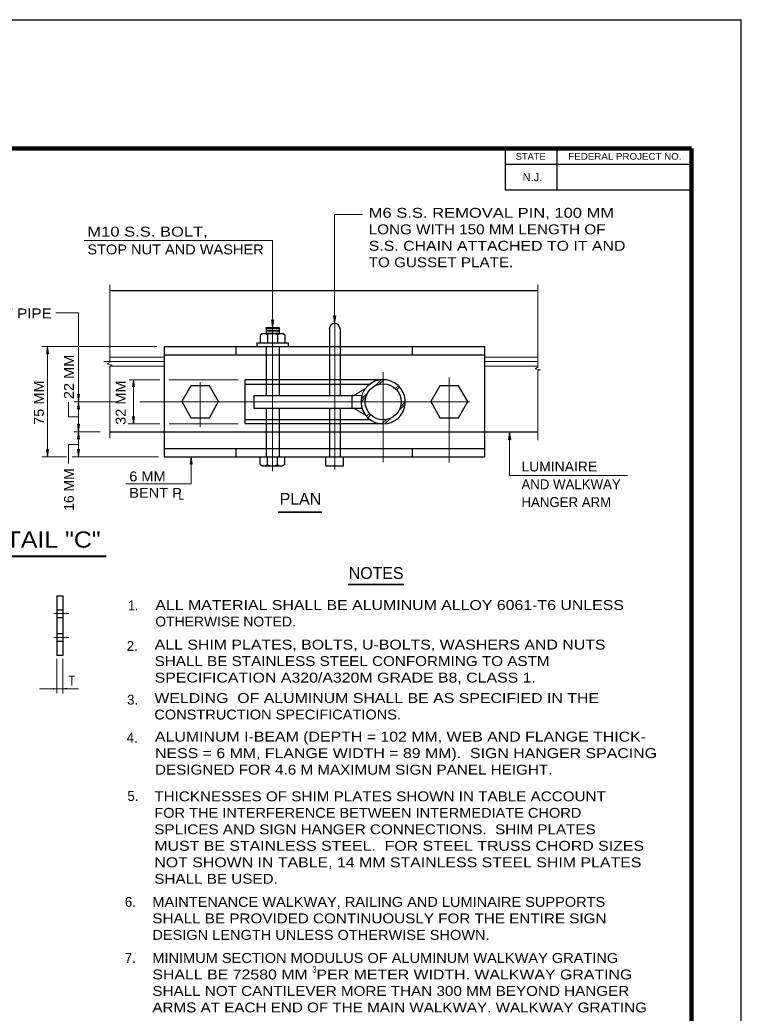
# Model space of a CAD drawing. Extents: x 312601.858 to 312602.699, y 144420.109 to 144420.704.
# Drawn here: x 312602.4801 to 312602.6988, y 144420.4024 to 144420.7035 of the extents above; entities that cross this region are included whole.
import ezdxf
from ezdxf.enums import TextEntityAlignment as Align

# ---------------------------------------------------------------- set-up
doc = ezdxf.new("R2010")
doc.units = 0
doc.header["$LTSCALE"] = 0.0012
for name, pattern in [('DOT_DASHED', [7.7, 5, -1.2, 0.3, -1.2]), ('LONG_DASHED', [7.5, 6, -1.5]), ('SHORT_DASHED', [2.7, 1.5, -1.2])]:
    doc.linetypes.add(name, pattern=pattern)
for name, color, linetype, lineweight in [('1', 7, 'Continuous', 13), ('2', 7, 'Continuous', 13), ('39', 7, 'Continuous', 13), ('61', 7, 'Continuous', 25)]:
    doc.layers.add(name, color=color, linetype=linetype, lineweight=lineweight)

msp = doc.modelspace()

# ---------------------------------------------------------------- hatches: boundary and pattern name
at = {"layer": '39'}
for points in [[(312602.5567, 144420.6124), (312602.5571, 144420.6126), (312602.5567, 144420.6102), (312602.5564, 144420.6126)], [(312602.5755, 144420.6136), (312602.5759, 144420.6138), (312602.5755, 144420.6114), (312602.5752, 144420.6138)], [(312602.6286, 144420.5764), (312602.6283, 144420.5762), (312602.6286, 144420.5786), (312602.629, 144420.5762)]]:
    msp.add_hatch(color=256, dxfattribs=at).paths.add_polyline_path(points)

# ---------------------------------------------------------------- linework, layer by layer
at = {"layer": '1'}
for p, q in [((312602.5755, 144420.6445), (312602.5755, 144420.6114)), ((312602.5757, 144420.6445), (312602.584, 144420.6445)), ((312602.4996, 144420.6366), (312602.5567, 144420.6366)), ((312602.5567, 144420.6366), (312602.5567, 144420.6102)), ((312602.5074, 144420.6232), (312602.5074, 144420.5997)), ((312602.6372, 144420.6233), (312602.6372, 144420.5982)), ((312602.5548, 144420.6098), (312602.5587, 144420.6098)), ((312602.5548, 144420.6093), (312602.5587, 144420.6093)), ((312602.5548, 144420.6089), (312602.5587, 144420.6089)), ((312602.4868, 144420.6045), (312602.5217, 144420.6045)), ((312602.4885, 144420.6045), (312602.4885, 144420.571)), ((312602.5066, 144420.5992), (312602.5073, 144420.5996)), ((312602.5066, 144420.5992), (312602.5081, 144420.5988)), ((312602.5074, 144420.5985), (312602.5081, 144420.5988)), ((312602.5074, 144420.5985), (312602.5074, 144420.5767)), ((312602.6364, 144420.5977), (312602.6372, 144420.5982)), ((312602.6364, 144420.5977), (312602.638, 144420.5974)), ((312602.6372, 144420.5971), (312602.638, 144420.5974)), ((312602.6372, 144420.5971), (312602.6372, 144420.5761)), ((312602.5226, 144420.5944), (312602.5133, 144420.5944)), ((312602.5146, 144420.5944), (312602.5146, 144420.581)), ((312602.5463, 144420.5944), (312602.5253, 144420.5944)), ((312602.5877, 144420.5925), (312602.5897, 144420.5944)), ((312602.589, 144420.593), (312602.5905, 144420.5944)), ((312602.5837, 144420.5886), (312602.5855, 144420.5903)), ((312602.5848, 144420.5916), (312602.5849, 144420.5917)), ((312602.5939, 144420.5917), (312602.5949, 144420.5926)), ((312602.5944, 144420.5913), (312602.5953, 144420.5922)), ((312602.4966, 144420.5877), (312602.5095, 144420.5877)), ((312602.5836, 144420.5877), (312602.585, 144420.5892)), ((312602.5956, 144420.5863), (312602.597, 144420.5878)), ((312602.5852, 144420.5834), (312602.5861, 144420.5842)), ((312602.5951, 144420.5852), (312602.5969, 144420.5869)), ((312602.5226, 144420.581), (312602.513, 144420.581)), ((312602.5463, 144420.581), (312602.5254, 144420.581)), ((312602.5848, 144420.5838), (312602.5849, 144420.5837)), ((312602.5856, 144420.5829), (312602.5865, 144420.5838)), ((312602.5899, 144420.581), (312602.5914, 144420.5824)), ((312602.5908, 144420.581), (312602.5927, 144420.5829)), ((312602.4965, 144420.5786), (312602.5045, 144420.5786)), ((312602.4868, 144420.571), (312602.4943, 144420.571)), ((312602.496, 144420.571), (312602.5222, 144420.571)), ((312602.4913, 144420.5098), (312602.4913, 144420.4994)), ((312602.4932, 144420.5098), (312602.4932, 144420.4993))]:
    msp.add_line(p, q, dxfattribs=at)
at = {"layer": '1', "lineweight": 25}
for p, q in [((312602.5074, 144420.6215), (312602.6372, 144420.6215)), ((312602.553, 144420.608), (312602.5536, 144420.6084)), ((312602.5536, 144420.6084), (312602.5599, 144420.6084)), ((312602.5548, 144420.6102), (312602.5587, 144420.6102)), ((312602.5548, 144420.6102), (312602.5548, 144420.6084)), ((312602.5587, 144420.6102), (312602.5587, 144420.6084)), ((312602.5605, 144420.608), (312602.5599, 144420.6084)), ((312602.574, 144420.6098), (312602.574, 144420.6045)), ((312602.5772, 144420.6098), (312602.5772, 144420.6045)), ((312602.552, 144420.6056), (312602.552, 144420.6045)), ((312602.552, 144420.6056), (312602.5615, 144420.6056)), ((312602.553, 144420.608), (312602.553, 144420.6056)), ((312602.5552, 144420.608), (312602.5552, 144420.6056)), ((312602.5582, 144420.608), (312602.5582, 144420.6056)), ((312602.5605, 144420.608), (312602.5605, 144420.6056)), ((312602.5615, 144420.6056), (312602.5615, 144420.6045)), ((312602.5239, 144420.6045), (312602.621, 144420.6045)), ((312602.5239, 144420.6045), (312602.5239, 144420.571)), ((312602.5456, 144420.6045), (312602.5456, 144420.602)), ((312602.5991, 144420.6045), (312602.5991, 144420.602)), ((312602.621, 144420.6045), (312602.621, 144420.571)), ((312602.5239, 144420.602), (312602.621, 144420.602)), ((312602.5548, 144420.602), (312602.5548, 144420.5944)), ((312602.5587, 144420.602), (312602.5587, 144420.5944)), ((312602.574, 144420.602), (312602.574, 144420.5944)), ((312602.5772, 144420.602), (312602.5772, 144420.5944)), ((312602.5483, 144420.5944), (312602.5483, 144420.581)), ((312602.5903, 144420.5944), (312602.5484, 144420.5944)), ((312602.5511, 144420.5896), (312602.5511, 144420.5858)), ((312602.5511, 144420.5896), (312602.5814, 144420.5896)), ((312602.5808, 144420.5896), (312602.5808, 144420.5858)), ((312602.5511, 144420.5858), (312602.5838, 144420.5858)), ((312602.5903, 144420.581), (312602.5483, 144420.581)), ((312602.5548, 144420.581), (312602.5548, 144420.5736)), ((312602.5587, 144420.581), (312602.5587, 144420.5736)), ((312602.574, 144420.581), (312602.574, 144420.5736)), ((312602.5772, 144420.581), (312602.5772, 144420.5736)), ((312602.5074, 144420.5786), (312602.5239, 144420.5786)), ((312602.621, 144420.5786), (312602.6372, 144420.5786)), ((312602.5239, 144420.5736), (312602.621, 144420.5736)), ((312602.5456, 144420.5736), (312602.5456, 144420.571)), ((312602.5991, 144420.5736), (312602.5991, 144420.571)), ((312602.5239, 144420.571), (312602.621, 144420.571)), ((312602.553, 144420.5687), (312602.553, 144420.571)), ((312602.5552, 144420.5687), (312602.5552, 144420.571)), ((312602.5582, 144420.5687), (312602.5582, 144420.571)), ((312602.5605, 144420.5687), (312602.5605, 144420.571)), ((312602.5729, 144420.5683), (312602.5729, 144420.571)), ((312602.5782, 144420.5683), (312602.5782, 144420.571)), ((312602.553, 144420.5687), (312602.5536, 144420.5683)), ((312602.5536, 144420.5683), (312602.5599, 144420.5683)), ((312602.5605, 144420.5687), (312602.5599, 144420.5683)), ((312602.5729, 144420.5683), (312602.5782, 144420.5683)), ((312602.4913, 144420.5289), (312602.4913, 144420.5108)), ((312602.4913, 144420.5289), (312602.4932, 144420.5289)), ((312602.4932, 144420.5289), (312602.4932, 144420.5108)), ((312602.4913, 144420.5246), (312602.4932, 144420.5246)), ((312602.4913, 144420.5223), (312602.4932, 144420.5223)), ((312602.4913, 144420.5175), (312602.4932, 144420.5175)), ((312602.4913, 144420.5151), (312602.4932, 144420.5151)), ((312602.4932, 144420.5108), (312602.4913, 144420.5108))]:
    msp.add_line(p, q, dxfattribs=at)
at = {"layer": '1', "linetype": 'DOT_DASHED'}
for p, q in [((312602.5756, 144420.6113), (312602.5756, 144420.5672)), ((312602.5567, 144420.6104), (312602.5567, 144420.5667)), ((312602.5056, 144420.5999), (312602.5239, 144420.5999)), ((312602.621, 144420.5999), (312602.6372, 144420.5999)), ((312602.5903, 144420.5967), (312602.5903, 144420.5694)), ((312602.5348, 144420.5937), (312602.5348, 144420.5801)), ((312602.6103, 144420.5951), (312602.6103, 144420.5693)), ((312602.6103, 144420.5937), (312602.6103, 144420.5801)), ((312602.5165, 144420.5877), (312602.6184, 144420.5877)), ((312602.495, 144420.5235), (312602.4904, 144420.5235)), ((312602.495, 144420.5163), (312602.4904, 144420.5163))]:
    msp.add_line(p, q, dxfattribs=at)
at = {"layer": '1', "linetype": 'SHORT_DASHED', "lineweight": 25}
for p, q in [((312602.5548, 144420.6045), (312602.5548, 144420.602)), ((312602.5587, 144420.6045), (312602.5587, 144420.602)), ((312602.574, 144420.6045), (312602.574, 144420.602)), ((312602.5772, 144420.6045), (312602.5772, 144420.602)), ((312602.5548, 144420.5944), (312602.5548, 144420.5896)), ((312602.5587, 144420.5944), (312602.5587, 144420.5896)), ((312602.574, 144420.5944), (312602.574, 144420.5896)), ((312602.5772, 144420.5944), (312602.5772, 144420.5896)), ((312602.5548, 144420.5858), (312602.5548, 144420.581)), ((312602.5587, 144420.5858), (312602.5587, 144420.581)), ((312602.574, 144420.5858), (312602.574, 144420.581)), ((312602.5772, 144420.5858), (312602.5772, 144420.581)), ((312602.5548, 144420.5736), (312602.5548, 144420.571)), ((312602.5587, 144420.5736), (312602.5587, 144420.571)), ((312602.574, 144420.5736), (312602.574, 144420.571)), ((312602.5772, 144420.5736), (312602.5772, 144420.571))]:
    msp.add_line(p, q, dxfattribs=at)
at = {"layer": '1', "linetype": 'LONG_DASHED'}
for p, q in [((312602.5074, 144420.6012), (312602.5239, 144420.6012)), ((312602.621, 144420.6012), (312602.6372, 144420.6012)), ((312602.5074, 144420.5985), (312602.5239, 144420.5985)), ((312602.621, 144420.5985), (312602.6372, 144420.5985))]:
    msp.add_line(p, q, dxfattribs=at)
at = {"layer": '1', "linetype": 'LONG_DASHED', "lineweight": 25}
for p, q in [((312602.5483, 144420.5931), (312602.5864, 144420.5931)), ((312602.5483, 144420.5823), (312602.5864, 144420.5823)), ((312602.5242, 144420.5786), (312602.621, 144420.5786))]:
    msp.add_line(p, q, dxfattribs=at)
at = {"layer": '1'}
for points in [[(312602.4979, 144420.6147), (312602.4979, 144420.5877), (312602.4979, 144420.5786), (312602.4979, 144420.571)], [(312602.5849, 144420.5917), (312602.5814, 144420.5896), (312602.5838, 144420.5896)], [(312602.5838, 144420.5896), (312602.5814, 144420.5896), (312602.5849, 144420.5917), (312602.5848, 144420.5916)], [(312602.5849, 144420.5837), (312602.5814, 144420.5858), (312602.5838, 144420.5858)], [(312602.6286, 144420.5786), (312602.6286, 144420.5654), (312602.6643, 144420.5654)], [(312602.5321, 144420.571), (312602.5321, 144420.5628), (312602.5123, 144420.5628)], [(312602.4861, 144420.5007), (312602.4913, 144420.5007), (312602.4932, 144420.5007), (312602.4979, 144420.5007)]]:
    msp.add_lwpolyline(points, dxfattribs=at)
for points in [[(312602.4882, 144420.6023), (312602.4885, 144420.6045), (312602.4888, 144420.6023), (312602.4885, 144420.6025)], [(312602.5143, 144420.5922), (312602.5146, 144420.5944), (312602.5149, 144420.5922), (312602.5146, 144420.5924)], [(312602.4982, 144420.59), (312602.4979, 144420.5877), (312602.4976, 144420.59), (312602.4979, 144420.5897)], [(312602.4976, 144420.5855), (312602.4979, 144420.5877), (312602.4982, 144420.5855), (312602.4979, 144420.5857)], [(312602.5149, 144420.5833), (312602.5146, 144420.581), (312602.5143, 144420.5833), (312602.5146, 144420.583)], [(312602.4982, 144420.5809), (312602.4979, 144420.5786), (312602.4976, 144420.5809), (312602.4979, 144420.5806)], [(312602.4976, 144420.5764), (312602.4979, 144420.5786), (312602.4982, 144420.5764), (312602.4979, 144420.5766)], [(312602.4888, 144420.5733), (312602.4885, 144420.571), (312602.4882, 144420.5733), (312602.4885, 144420.573)], [(312602.4982, 144420.5733), (312602.4979, 144420.571), (312602.4976, 144420.5733), (312602.4979, 144420.573)], [(312602.5318, 144420.5688), (312602.5321, 144420.571), (312602.5324, 144420.5688), (312602.5321, 144420.569)]]:
    msp.add_lwpolyline(points, close=True, dxfattribs=at)
at = {"layer": '1', "lineweight": 25}
for points in [[(312602.532, 144420.5829), (312602.5376, 144420.5829), (312602.5404, 144420.5878), (312602.5376, 144420.5926), (312602.532, 144420.5926), (312602.5292, 144420.5878)], [(312602.6075, 144420.5829), (312602.6131, 144420.5829), (312602.6159, 144420.5878), (312602.6131, 144420.5926), (312602.6075, 144420.5926), (312602.6047, 144420.5878)]]:
    msp.add_lwpolyline(points, close=True, dxfattribs=at)
msp.add_circle((312602.590285, 144420.587705), 0.00544, dxfattribs=at)
for centre, radius, start, end in [((312602.554075, 144420.60649), 0.001872, 53.82173, 116.36509), ((312602.559345, 144420.60649), 0.001872, 56.30993, 126.17827), ((312602.590285, 144420.587705), 0.006715, 163.83043, 143.98606), ((312602.554075, 144420.570195), 0.001872, 243.63491, 306.17827), ((312602.559345, 144420.570195), 0.001872, 233.82173, 296.36509)]:
    msp.add_arc(centre, radius, start, end, dxfattribs=at)
at = {"layer": '1'}
for centre, radius, start, end in [((312602.55671, 144420.604747), 0.003612, 64.94239, 115.05762), ((312602.590285, 144420.587705), 0.006715, 143.98606, 163.83043), ((312602.590285, 144420.587705), 0.006715, 143.98606, 163.83043), ((312602.590285, 144420.587705), 0.006715, 196.16957, 216.01394), ((312602.55671, 144420.571938), 0.003612, 244.94238, 295.05761)]:
    msp.add_arc(centre, radius, start, end, dxfattribs=at)
at = {"layer": '1', "lineweight": 25}
msp.add_ellipse((312602.57558, 144420.609805), major_axis=(0.001623, 0.000171), ratio=0.995348, start_param=6.1788327, end_param=9.319901, dxfattribs=at)
at = {"layer": '2'}
for p, q in [((312602.4979, 144420.6147), (312602.491, 144420.6147)), ((312602.4979, 144420.5748), (312602.4949, 144420.5748)), ((312602.4949, 144420.569), (312602.4949, 144420.5748))]:
    msp.add_line(p, q, dxfattribs=at)
at = {"layer": '2', "lineweight": 35}
for p, q in [((312602.5584, 144420.5543), (312602.5717, 144420.5543)), ((312602.5797, 144420.5323), (312602.5965, 144420.5323))]:
    msp.add_line(p, q, dxfattribs=at)
at = {"layer": '2', "lineweight": 40}
msp.add_line((312602.3981, 144420.5409), (312602.5063, 144420.5409), dxfattribs=at)
at = {"layer": '2'}
msp.add_lwpolyline([(312602.4979, 144420.5832), (312602.4949, 144420.5832), (312602.4949, 144420.5876)], dxfattribs=at)
for points in [[(312602.4902, 144420.5008), (312602.4913, 144420.5007), (312602.4902, 144420.5006), (312602.4903, 144420.5007)], [(312602.4943, 144420.5006), (312602.4932, 144420.5007), (312602.4943, 144420.5009), (312602.4942, 144420.5007)]]:
    msp.add_lwpolyline(points, close=True, dxfattribs=at)
at = {"layer": '39', "lineweight": 25}
for p, q in [((312601.8578, 144420.7035), (312602.6988, 144420.7035)), ((312602.6988, 144420.1095), (312602.6988, 144420.7035)), ((312602.5735, 144420.6645), (312602.6838, 144420.6645)), ((312602.6838, 144420.6514), (312602.6838, 144420.6645))]:
    msp.add_line(p, q, dxfattribs=at)
at = {"layer": '39', "lineweight": 158}
for p in [(312601.9088, 144420.6645), (312602.6838, 144420.1247)]:
    msp.add_line(p, (312602.6838, 144420.6645), dxfattribs=at)
at = {"layer": '39'}
for points in [[(312602.5567, 144420.6124), (312602.5571, 144420.6126), (312602.5567, 144420.6102), (312602.5564, 144420.6126)], [(312602.5755, 144420.6136), (312602.5759, 144420.6138), (312602.5755, 144420.6114), (312602.5752, 144420.6138)], [(312602.6286, 144420.5764), (312602.6283, 144420.5762), (312602.6286, 144420.5786), (312602.629, 144420.5762)]]:
    msp.add_lwpolyline(points, close=True, dxfattribs=at)
at = {"layer": '61'}
for p, q in [((312602.6273, 144420.6645), (312602.6273, 144420.6519)), ((312602.6429, 144420.6645), (312602.6429, 144420.6519)), ((312602.6838, 144420.6597), (312602.6273, 144420.6597)), ((312602.6838, 144420.6519), (312602.6273, 144420.6519))]:
    msp.add_line(p, q, dxfattribs=at)

# ---------------------------------------------------------------- texts
at = {"layer": '2'}
for s, height, width, p in [('M6 S.S. REMOVAL PIN, 100 MM', 0.003, 1.25, (312602.5859, 144420.6435)), ('LONG WITH 150 MM LENGTH OF', 0.003, 1.15, (312602.5859, 144420.6385)), ('M10 S.S. BOLT,', 0.003, 1.25, (312602.5006, 144420.6378)), ('STOP NUT AND WASHER', 0.003, 1.1, (312602.5006, 144420.6324)), ('S.S. CHAIN ATTACHED TO IT AND', 0.003, 1.2, (312602.5859, 144420.6335)), ('TO GUSSET PLATE.', 0.003, 1.15, (312602.5859, 144420.6285)), ('OF PIPE', 0.003, 1.15, (312602.4716, 144420.613)), ('LUMINAIRE', 0.003, 1.05, (312602.6322, 144420.5666)), ('6 MM', 0.003, 1.1, (312602.5133, 144420.5636)), ('BENT P', 0.003, 1.1, (312602.5133, 144420.5586)), ('HANDRAIL HINGE DETAIL "C"', 0.0049, 1.15, (312602.3992, 144420.5435)), ('ALL MATERIAL SHALL BE ALUMINUM ALLOY 6061-T6 UNLESS', 0.003, 1.2, (312602.5212, 144420.5246)), ('OTHERWISE NOTED.', 0.003, 1.05, (312602.5212, 144420.5196)), ('ALL SHIM PLATES, BOLTS, U-BOLTS, WASHERS AND NUTS', 0.003, 1.2, (312602.521, 144420.5126)), ('SHALL BE STAINLESS STEEL CONFORMING TO ASTM ', 0.003, 1.15, (312602.521, 144420.5076)), ('SPECIFICATION A320/A320M GRADE B8, CLASS 1.', 0.003, 1.2, (312602.521, 144420.5026)), ('WELDING  OF ALUMINUM SHALL BE AS SPECIFIED IN THE', 0.003, 1.2, (312602.5209, 144420.4964)), ('CONSTRUCTION SPECIFICATIONS.', 0.003, 1.1, (312602.5209, 144420.4914)), ('ALUMINUM I-BEAM (DEPTH = 102 MM, WEB AND FLANGE THICK-', 0.003, 1.2, (312602.5211, 144420.4847)), ('NESS = 6 MM, FLANGE WIDTH = 89 MM).  SIGN HANGER SPACING', 0.003, 1.2, (312602.5211, 144420.4797)), ('DESIGNED FOR 4.6 M MAXIMUM SIGN PANEL HEIGHT.', 0.003, 1.15, (312602.5211, 144420.4747)), ('THICKNESSES OF SHIM PLATES SHOWN IN TABLE ACCOUNT', 0.003, 1.15, (312602.5209, 144420.4666)), ('FOR THE INTERFERENCE BETWEEN INTERMEDIATE CHORD', 0.003, 1.1, (312602.5209, 144420.4616)), ('SPLICES AND SIGN HANGER CONNECTIONS.  SHIM PLATES', 0.003, 1.15, (312602.5209, 144420.4566)), ('MUST BE STAINLESS STEEL.  FOR STEEL TRUSS CHORD SIZES', 0.003, 1.2, (312602.5209, 144420.4516)), ('NOT SHOWN IN TABLE, 14 MM STAINLESS STEEL SHIM PLATES', 0.003, 1.2, (312602.5209, 144420.4466)), ('SHALL BE USED.', 0.003, 1.15, (312602.5209, 144420.4416)), ('MAINTENANCE WALKWAY, RAILING AND LUMINAIRE SUPPORTS', 0.003, 1.1, (312602.5203, 144420.4346)), ('SHALL BE PROVIDED CONTINUOUSLY FOR THE ENTIRE SIGN', 0.003, 1.15, (312602.5203, 144420.4296)), ('DESIGN LENGTH UNLESS OTHERWISE SHOWN.', 0.003, 1.1, (312602.5203, 144420.4246)), ('MINIMUM SECTION MODULUS OF ALUMINUM WALKWAY GRATING', 0.003, 1.1, (312602.5203, 144420.4176)), ('SHALL BE 72580 MM  PER METER WIDTH. WALKWAY GRATING ', 0.003, 1.2, (312602.5203, 144420.4126)), ('SHALL NOT CANTILEVER MORE THAN 300 MM BEYOND HANGER', 0.003, 1.15, (312602.5203, 144420.4076)), ('ARMS AT EACH END OF THE MAIN WALKWAY. WALKWAY GRATING ', 0.003, 1.15, (312602.5203, 144420.4026))]:
    msp.add_text(s, height=height, dxfattribs=dict(at, width=width)).set_placement(p)
for s, width, p in [('22 MM', 1.1, (312602.4965, 144420.59525)), ('75 MM', 1.1, (312602.4874, 144420.58745)), ('32 MM', 1.1, (312602.5122, 144420.58745)), ('16 MM', 1.05, (312602.4965, 144420.5611))]:
    msp.add_text(s, height=0.003, rotation=90, dxfattribs=dict(at, width=width)).set_placement(p, align=Align.CENTER)
for s, height, p in [('AND WALKWAY', 0.003, (312602.6322, 144420.5612)), ('PLAN', 0.0036, (312602.5589, 144420.5565)), ('HANGER ARM', 0.003, (312602.6322, 144420.5558))]:
    msp.add_text(s, height=height, dxfattribs=at).set_placement(p)
for s, height, width, p in [('L', 0.003, 0.75, (312602.52905, 144420.558)), ('1.', 0.003, 0.9, (312602.5145, 144420.5245)), ('T', 0.003, 0.8, (312602.49585, 144420.5017)), ('3', 0.002, 0.75, (312602.56945, 144420.4146))]:
    msp.add_text(s, height=height, dxfattribs=dict(at, width=width)).set_placement(p, align=Align.CENTER)
for s, height, p in [('NOTES', 0.0036, (312602.58815, 144420.534)), ('2.', 0.003, (312602.5142, 144420.5122)), ('3.', 0.003, (312602.5143, 144420.4959)), ('4.', 0.003, (312602.5142, 144420.4844)), ('5.', 0.003, (312602.5144, 144420.4667)), ('6.', 0.003, (312602.51365, 144420.4346)), ('7.', 0.003, (312602.5136, 144420.4176))]:
    msp.add_text(s, height=height, dxfattribs=at).set_placement(p, align=Align.CENTER)
at = {"layer": '61'}
for s, width, p in [('STATE', 1.05, (312602.635, 144420.6611)), ('FEDERAL PROJECT NO.', 1.1, (312602.66355, 144420.6611))]:
    msp.add_text(s, height=0.00201, dxfattribs=dict(at, width=width)).set_placement(p, align=Align.CENTER)
msp.add_text('N.J.', height=0.002512, dxfattribs=at).set_placement((312602.63555, 144420.6546), align=Align.CENTER)

doc.saveas('drawing.dxf')
